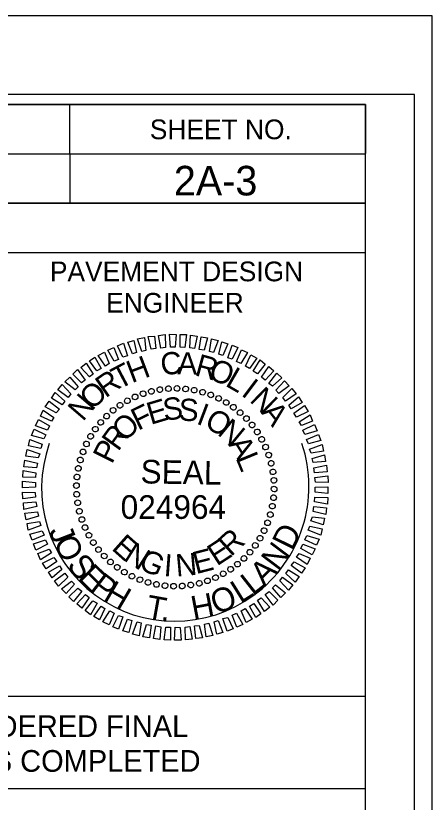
# Model space of a CAD drawing. Extents: x 1640342 to 1730599, y 538663 to 843747.
# Drawn here: x 1730156.25 to 1730177.39, y 539804.62 to 539844.5 of the extents above; entities that cross this region are included whole.
import ezdxf

# ---------------------------------------------------------------- set-up
doc = ezdxf.new("R2010")
doc.units = 0
for name, color, linetype in [('Sheet Data Field CELL', 7, 'Continuous'), ('Sheet PE Seal Cell', 7, 'Continuous'), ('Sheet Plan CELL', 7, 'Continuous'), ('Sheet Plan Layout CELL', 7, 'Continuous'), ('Sheet Plot Border Inside CELL', 7, 'Continuous'), ('Sheet Plot Border Outside CELL', 7, 'Continuous'), ('Sheet Sticker Exception Certification CELL', 7, 'Continuous')]:
    doc.layers.add(name, color=color, linetype=linetype)

msp = doc.modelspace()

# ---------------------------------------------------------------- linework, layer by layer
at = {"layer": 'Sheet PE Seal Cell'}
for p, q in [((1730162.709, 539825.337), (1730162.709, 539825.337)), ((1730163.129, 539825.457), (1730163.129, 539825.457)), ((1730163.569, 539825.537), (1730163.569, 539825.537)), ((1730163.999, 539825.597), (1730163.999, 539825.597)), ((1730164.439, 539825.607), (1730164.439, 539825.607)), ((1730164.879, 539825.577), (1730164.879, 539825.577)), ((1730165.309, 539825.507), (1730165.309, 539825.507)), ((1730165.729, 539825.417), (1730165.729, 539825.417)), ((1730166.149, 539825.277), (1730166.149, 539825.277)), ((1730161.919, 539824.977), (1730161.919, 539824.977)), ((1730162.309, 539825.177), (1730162.309, 539825.177)), ((1730166.549, 539825.097), (1730166.549, 539825.097)), ((1730166.939, 539824.897), (1730166.939, 539824.897)), ((1730161.189, 539824.497), (1730161.189, 539824.497)), ((1730161.539, 539824.747), (1730161.539, 539824.747)), ((1730167.299, 539824.647), (1730167.299, 539824.647)), ((1730160.859, 539824.197), (1730160.859, 539824.197)), ((1730167.649, 539824.377), (1730167.649, 539824.377)), ((1730167.959, 539824.077), (1730167.959, 539824.077)), ((1730160.559, 539823.887), (1730160.559, 539823.887)), ((1730168.259, 539823.747), (1730168.259, 539823.747)), ((1730160.289, 539823.537), (1730160.289, 539823.537)), ((1730168.509, 539823.397), (1730168.509, 539823.397)), ((1730160.039, 539823.177), (1730160.039, 539823.177)), ((1730168.739, 539823.017), (1730168.739, 539823.017)), ((1730159.839, 539822.787), (1730159.839, 539822.787)), ((1730168.939, 539822.627), (1730168.939, 539822.627)), ((1730159.659, 539822.387), (1730159.659, 539822.387)), ((1730169.099, 539822.227), (1730169.099, 539822.227)), ((1730159.519, 539821.967), (1730159.519, 539821.967)), ((1730169.219, 539821.807), (1730169.219, 539821.807)), ((1730159.429, 539821.547), (1730159.429, 539821.547)), ((1730169.299, 539821.367), (1730169.299, 539821.367)), ((1730159.359, 539821.117), (1730159.359, 539821.117)), ((1730169.359, 539820.937), (1730169.359, 539820.937)), ((1730159.329, 539820.677), (1730159.329, 539820.677)), ((1730169.369, 539820.497), (1730169.369, 539820.497)), ((1730159.339, 539820.237), (1730159.339, 539820.237)), ((1730169.339, 539820.057), (1730169.339, 539820.057)), ((1730159.399, 539819.807), (1730159.399, 539819.807)), ((1730169.269, 539819.627), (1730169.269, 539819.627)), ((1730159.479, 539819.367), (1730159.479, 539819.367)), ((1730159.599, 539818.947), (1730159.599, 539818.947)), ((1730169.179, 539819.207), (1730169.179, 539819.207)), ((1730159.759, 539818.547), (1730159.759, 539818.547)), ((1730169.039, 539818.787), (1730169.039, 539818.787)), ((1730159.959, 539818.157), (1730159.959, 539818.157)), ((1730168.859, 539818.387), (1730168.859, 539818.387)), ((1730160.189, 539817.777), (1730160.189, 539817.777)), ((1730168.409, 539817.637), (1730168.409, 539817.637)), ((1730168.659, 539817.997), (1730168.659, 539817.997)), ((1730160.439, 539817.427), (1730160.439, 539817.427)), ((1730168.139, 539817.287), (1730168.139, 539817.287)), ((1730160.739, 539817.097), (1730160.739, 539817.097)), ((1730167.839, 539816.977), (1730167.839, 539816.977)), ((1730161.049, 539816.797), (1730161.049, 539816.797)), ((1730161.399, 539816.527), (1730161.399, 539816.527)), ((1730167.509, 539816.677), (1730167.509, 539816.677)), ((1730161.759, 539816.277), (1730161.759, 539816.277)), ((1730162.149, 539816.077), (1730162.149, 539816.077)), ((1730166.779, 539816.197), (1730166.779, 539816.197)), ((1730167.159, 539816.427), (1730167.159, 539816.427)), ((1730162.549, 539815.897), (1730162.549, 539815.897)), ((1730162.969, 539815.757), (1730162.969, 539815.757)), ((1730163.389, 539815.667), (1730163.389, 539815.667)), ((1730165.129, 539815.637), (1730165.129, 539815.637)), ((1730165.569, 539815.717), (1730165.569, 539815.717)), ((1730165.989, 539815.837), (1730165.989, 539815.837)), ((1730166.389, 539815.997), (1730166.389, 539815.997)), ((1730163.819, 539815.597), (1730163.819, 539815.597)), ((1730164.259, 539815.567), (1730164.259, 539815.567)), ((1730164.699, 539815.577), (1730164.699, 539815.577))]:
    msp.add_line(p, q, dxfattribs=at)
for points in [[(1730162.169, 539827.347), (1730161.939, 539827.947), (1730162.249, 539828.037), (1730162.379, 539827.417)], [(1730162.649, 539827.477), (1730162.439, 539828.107), (1730162.779, 539828.177), (1730162.859, 539827.527)], [(1730163.129, 539827.587), (1730162.969, 539828.227), (1730163.299, 539828.257), (1730163.369, 539827.617)], [(1730163.609, 539827.647), (1730163.499, 539828.287), (1730163.839, 539828.327), (1730163.849, 539827.677)], [(1730164.109, 539827.697), (1730164.059, 539828.347), (1730164.389, 539828.337), (1730164.349, 539827.687)], [(1730164.589, 539827.687), (1730164.589, 539828.337), (1730164.919, 539828.327), (1730164.829, 539827.677)], [(1730165.089, 539827.657), (1730165.129, 539828.307), (1730165.459, 539828.247), (1730165.329, 539827.617)], [(1730165.569, 539827.577), (1730165.659, 539828.217), (1730165.989, 539828.167), (1730165.809, 539827.547)], [(1730166.079, 539827.467), (1730166.179, 539828.117), (1730166.519, 539828.037), (1730166.289, 539827.417)], [(1730161.239, 539826.977), (1730160.919, 539827.537), (1730161.229, 539827.677), (1730161.459, 539827.067)], [(1730161.679, 539827.187), (1730161.419, 539827.767), (1730161.719, 539827.887), (1730161.929, 539827.247)], [(1730166.559, 539827.337), (1730166.709, 539827.957), (1730167.019, 539827.857), (1730166.769, 539827.267)], [(1730167.009, 539827.157), (1730167.239, 539827.787), (1730167.519, 539827.667), (1730167.239, 539827.087)], [(1730160.809, 539826.737), (1730160.439, 539827.277), (1730160.749, 539827.437), (1730160.999, 539826.857)], [(1730167.459, 539826.967), (1730167.709, 539827.557), (1730168.019, 539827.417), (1730167.679, 539826.857)], [(1730167.919, 539826.737), (1730168.189, 539827.307), (1730168.489, 539827.137), (1730168.109, 539826.617)], [(1730159.989, 539826.187), (1730159.559, 539826.667), (1730159.829, 539826.877), (1730160.179, 539826.317)], [(1730160.369, 539826.487), (1730159.999, 539826.997), (1730160.259, 539827.187), (1730160.589, 539826.607)], [(1730168.309, 539826.467), (1730168.659, 539827.047), (1730168.919, 539826.837), (1730168.529, 539826.347)], [(1730159.589, 539825.877), (1730159.149, 539826.317), (1730159.389, 539826.557), (1730159.779, 539826.017)], [(1730168.719, 539826.167), (1730169.089, 539826.717), (1730169.349, 539826.497), (1730168.909, 539826.027)], [(1730159.259, 539825.527), (1730158.749, 539825.937), (1730158.999, 539826.167), (1730159.419, 539825.687)], [(1730169.099, 539825.857), (1730169.509, 539826.377), (1730169.749, 539826.137), (1730169.289, 539825.707)], [(1730158.909, 539825.147), (1730158.389, 539825.537), (1730158.609, 539825.797), (1730159.049, 539825.327)], [(1730169.459, 539825.507), (1730169.889, 539825.977), (1730170.129, 539825.737), (1730169.609, 539825.347)], [(1730158.609, 539824.767), (1730158.069, 539825.107), (1730158.259, 539825.397), (1730158.739, 539824.957)], [(1730169.809, 539825.147), (1730170.269, 539825.597), (1730170.479, 539825.327), (1730169.949, 539824.947)], [(1730158.309, 539824.367), (1730157.749, 539824.667), (1730157.949, 539824.947), (1730158.469, 539824.547)], [(1730170.109, 539824.757), (1730170.599, 539825.177), (1730170.789, 539824.887), (1730170.229, 539824.567)], [(1730158.069, 539823.937), (1730157.499, 539824.187), (1730157.649, 539824.497), (1730158.189, 539824.127)], [(1730170.369, 539824.347), (1730170.899, 539824.727), (1730171.089, 539824.427), (1730170.509, 539824.147)], [(1730157.869, 539823.477), (1730157.249, 539823.707), (1730157.399, 539824.017), (1730157.969, 539823.697)], [(1730170.629, 539823.907), (1730171.189, 539824.257), (1730171.319, 539823.947), (1730170.749, 539823.717)], [(1730170.829, 539823.477), (1730171.419, 539823.777), (1730171.549, 539823.457), (1730170.929, 539823.257)], [(1730157.669, 539823.037), (1730157.049, 539823.217), (1730157.179, 539823.527), (1730157.779, 539823.247)], [(1730171.009, 539823.007), (1730171.619, 539823.267), (1730171.729, 539822.957), (1730171.109, 539822.797)], [(1730157.519, 539822.557), (1730156.899, 539822.687), (1730156.969, 539823.017), (1730157.599, 539822.767)], [(1730157.389, 539822.077), (1730156.769, 539822.157), (1730156.839, 539822.497), (1730157.469, 539822.287)], [(1730171.169, 539822.527), (1730171.809, 539822.757), (1730171.869, 539822.427), (1730171.239, 539822.317)], [(1730171.289, 539822.047), (1730171.919, 539822.237), (1730171.979, 539821.897), (1730171.349, 539821.837)], [(1730157.309, 539821.567), (1730156.669, 539821.627), (1730156.709, 539821.967), (1730157.359, 539821.807)], [(1730171.379, 539821.567), (1730172.029, 539821.707), (1730172.059, 539821.367), (1730171.419, 539821.327)], [(1730157.259, 539821.087), (1730156.609, 539821.107), (1730156.629, 539821.437), (1730157.279, 539821.327)], [(1730157.249, 539820.587), (1730156.599, 539820.557), (1730156.599, 539820.897), (1730157.249, 539820.827)], [(1730171.439, 539821.087), (1730172.089, 539821.167), (1730172.109, 539820.827), (1730171.459, 539820.847)], [(1730171.449, 539820.587), (1730172.099, 539820.617), (1730172.099, 539820.277), (1730171.449, 539820.347)], [(1730157.259, 539820.087), (1730156.609, 539820.007), (1730156.589, 539820.347), (1730157.239, 539820.327)], [(1730171.439, 539820.087), (1730172.089, 539820.067), (1730172.069, 539819.737), (1730171.419, 539819.847)], [(1730157.319, 539819.607), (1730156.669, 539819.467), (1730156.639, 539819.807), (1730157.279, 539819.847)], [(1730157.409, 539819.127), (1730156.779, 539818.937), (1730156.719, 539819.277), (1730157.349, 539819.337)], [(1730171.389, 539819.607), (1730172.029, 539819.547), (1730171.989, 539819.207), (1730171.339, 539819.367)], [(1730157.529, 539818.647), (1730156.889, 539818.417), (1730156.829, 539818.747), (1730157.459, 539818.857)], [(1730171.309, 539819.097), (1730171.929, 539819.017), (1730171.859, 539818.677), (1730171.229, 539818.887)], [(1730171.179, 539818.617), (1730171.799, 539818.487), (1730171.729, 539818.157), (1730171.099, 539818.407)], [(1730157.689, 539818.167), (1730157.079, 539817.907), (1730156.969, 539818.217), (1730157.589, 539818.377)], [(1730171.029, 539818.137), (1730171.649, 539817.957), (1730171.519, 539817.647), (1730170.919, 539817.927)], [(1730157.869, 539817.697), (1730157.279, 539817.397), (1730157.149, 539817.717), (1730157.769, 539817.917)], [(1730170.829, 539817.697), (1730171.449, 539817.467), (1730171.299, 539817.157), (1730170.729, 539817.477)], [(1730158.069, 539817.267), (1730157.509, 539816.917), (1730157.379, 539817.227), (1730157.949, 539817.457)], [(1730170.629, 539817.237), (1730171.199, 539816.987), (1730171.049, 539816.677), (1730170.509, 539817.047)], [(1730158.329, 539816.827), (1730157.799, 539816.447), (1730157.609, 539816.747), (1730158.189, 539817.027)], [(1730158.589, 539816.417), (1730158.099, 539815.997), (1730157.909, 539816.287), (1730158.469, 539816.607)], [(1730170.389, 539816.807), (1730170.949, 539816.507), (1730170.749, 539816.227), (1730170.229, 539816.627)], [(1730158.889, 539816.027), (1730158.429, 539815.577), (1730158.219, 539815.847), (1730158.749, 539816.227)], [(1730170.089, 539816.407), (1730170.629, 539816.067), (1730170.439, 539815.777), (1730169.959, 539816.217)], [(1730159.239, 539815.667), (1730158.809, 539815.197), (1730158.569, 539815.437), (1730159.089, 539815.827)], [(1730169.439, 539815.647), (1730169.949, 539815.237), (1730169.699, 539815.007), (1730169.279, 539815.487)], [(1730169.789, 539816.027), (1730170.309, 539815.637), (1730170.089, 539815.377), (1730169.649, 539815.847)], [(1730159.599, 539815.317), (1730159.189, 539814.797), (1730158.949, 539815.037), (1730159.409, 539815.467)], [(1730169.109, 539815.297), (1730169.549, 539814.857), (1730169.309, 539814.617), (1730168.919, 539815.157)], [(1730159.979, 539815.007), (1730159.609, 539814.457), (1730159.349, 539814.677), (1730159.789, 539815.147)], [(1730168.709, 539814.987), (1730169.139, 539814.507), (1730168.869, 539814.297), (1730168.519, 539814.857)], [(1730160.389, 539814.707), (1730160.039, 539814.127), (1730159.779, 539814.337), (1730160.169, 539814.827)], [(1730160.779, 539814.437), (1730160.509, 539813.867), (1730160.209, 539814.037), (1730160.589, 539814.557)], [(1730168.329, 539814.687), (1730168.699, 539814.177), (1730168.439, 539813.987), (1730168.109, 539814.567)], [(1730161.239, 539814.207), (1730160.989, 539813.617), (1730160.679, 539813.757), (1730161.019, 539814.317)], [(1730161.689, 539814.017), (1730161.459, 539813.387), (1730161.179, 539813.507), (1730161.459, 539814.087)], [(1730167.459, 539814.197), (1730167.779, 539813.637), (1730167.469, 539813.497), (1730167.239, 539814.107)], [(1730167.889, 539814.437), (1730168.259, 539813.897), (1730167.949, 539813.737), (1730167.699, 539814.317)], [(1730162.139, 539813.837), (1730161.989, 539813.217), (1730161.679, 539813.317), (1730161.929, 539813.907)], [(1730162.619, 539813.707), (1730162.519, 539813.057), (1730162.179, 539813.137), (1730162.409, 539813.757)], [(1730166.049, 539813.697), (1730166.259, 539813.067), (1730165.919, 539812.997), (1730165.839, 539813.647)], [(1730166.529, 539813.827), (1730166.759, 539813.227), (1730166.449, 539813.137), (1730166.319, 539813.757)], [(1730167.019, 539813.987), (1730167.279, 539813.407), (1730166.979, 539813.287), (1730166.769, 539813.927)], [(1730163.129, 539813.597), (1730163.039, 539812.957), (1730162.709, 539813.007), (1730162.889, 539813.627)], [(1730163.609, 539813.517), (1730163.569, 539812.867), (1730163.239, 539812.927), (1730163.369, 539813.557)], [(1730164.109, 539813.487), (1730164.109, 539812.837), (1730163.779, 539812.847), (1730163.869, 539813.497)], [(1730164.589, 539813.477), (1730164.639, 539812.827), (1730164.309, 539812.837), (1730164.349, 539813.487)], [(1730165.089, 539813.527), (1730165.199, 539812.887), (1730164.859, 539812.847), (1730164.849, 539813.497)], [(1730165.569, 539813.587), (1730165.729, 539812.947), (1730165.399, 539812.917), (1730165.329, 539813.557)]]:
    msp.add_lwpolyline(points, close=True, dxfattribs=at)
for centre, major_axis in [((1730163.136, 539825.454), (-0.035, 0.14)), ((1730163.565, 539825.541), (-0.023, 0.142)), ((1730163.999, 539825.591), (-0.01, 0.144)), ((1730164.437, 539825.602), (0.003, 0.144)), ((1730164.874, 539825.575), (0.015, 0.143)), ((1730165.306, 539825.511), (0.027, 0.141)), ((1730162.309, 539825.169), (-0.059, 0.132)), ((1730162.716, 539825.33), (-0.047, 0.136)), ((1730165.732, 539825.409), (0.04, 0.138)), ((1730166.147, 539825.27), (0.052, 0.134)), ((1730166.548, 539825.095), (0.063, 0.129)), ((1730161.544, 539824.745), (-0.081, 0.119)), ((1730161.918, 539824.974), (-0.07, 0.126)), ((1730166.933, 539824.886), (0.074, 0.123)), ((1730161.193, 539824.485), (-0.091, 0.112)), ((1730167.298, 539824.645), (0.085, 0.116)), ((1730167.64, 539824.373), (0.094, 0.109)), ((1730160.564, 539823.878), (-0.109, 0.094)), ((1730160.865, 539824.195), (-0.1, 0.104)), ((1730167.958, 539824.071), (0.104, 0.1)), ((1730160.291, 539823.535), (-0.116, 0.085)), ((1730168.247, 539823.744), (0.112, 0.091)), ((1730160.05, 539823.17), (-0.123, 0.074)), ((1730168.508, 539823.392), (0.119, 0.081)), ((1730159.841, 539822.786), (-0.129, 0.063)), ((1730168.736, 539823.019), (0.126, 0.07)), ((1730159.666, 539822.385), (-0.134, 0.052)), ((1730168.932, 539822.627), (0.132, 0.059)), ((1730159.528, 539821.97), (-0.138, 0.04)), ((1730169.092, 539822.22), (0.136, 0.047)), ((1730159.425, 539821.544), (-0.141, 0.027)), ((1730169.216, 539821.8), (0.14, 0.035)), ((1730159.361, 539821.111), (-0.143, 0.015)), ((1730169.304, 539821.372), (0.142, 0.023)), ((1730169.353, 539820.937), (0.144, 0.01)), ((1730159.334, 539820.674), (-0.144, 0.003)), ((1730169.365, 539820.499), (0.144, -0.003)), ((1730159.346, 539820.237), (-0.144, -0.01)), ((1730169.338, 539820.063), (0.143, -0.015)), ((1730159.395, 539819.802), (-0.142, -0.023)), ((1730169.273, 539819.63), (0.141, -0.027)), ((1730159.482, 539819.373), (-0.14, -0.035)), ((1730169.171, 539819.204), (0.138, -0.04)), ((1730159.607, 539818.954), (-0.136, -0.047)), ((1730169.032, 539818.789), (0.134, -0.052)), ((1730159.767, 539818.547), (-0.132, -0.059)), ((1730168.858, 539818.388), (0.129, -0.063)), ((1730159.962, 539818.155), (-0.126, -0.07)), ((1730168.649, 539818.004), (0.123, -0.074)), ((1730160.191, 539817.782), (-0.119, -0.081)), ((1730168.407, 539817.639), (0.116, -0.085)), ((1730160.451, 539817.43), (-0.112, -0.091)), ((1730160.741, 539817.103), (-0.104, -0.1)), ((1730168.135, 539817.296), (0.109, -0.094)), ((1730161.059, 539816.801), (-0.094, -0.109)), ((1730167.506, 539816.689), (0.091, -0.112)), ((1730167.834, 539816.979), (0.1, -0.104)), ((1730161.401, 539816.529), (-0.085, -0.116)), ((1730161.766, 539816.287), (-0.074, -0.123)), ((1730167.154, 539816.428), (0.081, -0.119)), ((1730162.15, 539816.079), (-0.063, -0.129)), ((1730162.552, 539815.904), (-0.052, -0.134)), ((1730166.39, 539816.005), (0.059, -0.132)), ((1730166.781, 539816.2), (0.07, -0.126)), ((1730162.967, 539815.765), (-0.04, -0.138)), ((1730163.392, 539815.663), (-0.027, -0.141)), ((1730163.825, 539815.598), (-0.015, -0.143)), ((1730164.262, 539815.572), (-0.003, -0.144)), ((1730164.699, 539815.583), (0.01, -0.144)), ((1730165.134, 539815.633), (0.023, -0.142)), ((1730165.563, 539815.72), (0.035, -0.14)), ((1730165.982, 539815.844), (0.047, -0.136))]:
    msp.add_ellipse(centre, major_axis=major_axis, ratio=0.999708, dxfattribs=at)
at = {"layer": 'Sheet Plan CELL'}
for p, q in [((1730158.985, 539839.988), (1730158.995, 539834.988)), ((1730133.98, 539837.493), (1730173.99, 539837.491)), ((1730133.983, 539834.986), (1730173.99, 539834.991)), ((1730133.983, 539834.986), (1730173.99, 539834.991))]:
    msp.add_line(p, q, dxfattribs=at)
for points in [[(1729873.99, 539630.001), (1729873.985, 539839.996), (1730133.983, 539840.003), (1730133.985, 539809.991), (1730173.993, 539809.988), (1730173.993, 539630.001)], [(1730173.998, 539840.001), (1729873.99, 539840.001), (1729873.99, 539630.001), (1730173.993, 539630.001)], [(1730133.983, 539840.003), (1730173.998, 539840.001), (1730173.99, 539834.991), (1730133.983, 539834.986)], [(1730153.993, 539832.488), (1730173.99, 539832.491), (1730173.993, 539809.988), (1730153.993, 539809.986)]]:
    msp.add_lwpolyline(points, close=True, dxfattribs=at)
at = {"layer": 'Sheet Plan Layout CELL'}
msp.add_lwpolyline([(1730126.14, 539797.703), (1730173.995, 539797.703), (1730174, 539840.001), (1730126.14, 539840.001)], close=True, dxfattribs=at)
at = {"layer": 'Sheet Plot Border Inside CELL'}
msp.add_lwpolyline([(1729843.293, 539629.498), (1730176.49, 539629.501), (1730176.493, 539840.498), (1729843.293, 539840.498)], close=True, dxfattribs=at)
at = {"layer": 'Sheet Plot Border Outside CELL'}
msp.add_lwpolyline([(1729840.693, 539625.498), (1730177.393, 539625.498), (1730177.393, 539844.498), (1729840.693, 539844.498)], close=True, dxfattribs=at)
msp.add_ellipse((1730164.349, 539820.587), major_axis=(4.509, 5.104), ratio=0.993455, start_param=1.958957, end_param=5.764947, dxfattribs=at)
at = {"layer": 'Sheet Sticker Exception Certification CELL'}
for p, q in [((1730133.985, 539809.991), (1730173.993, 539809.991)), ((1730133.985, 539809.991), (1730173.993, 539809.991)), ((1730173.993, 539809.988), (1730173.993, 539805.288)), ((1730173.993, 539809.988), (1730173.993, 539805.288)), ((1730173.993, 539805.291), (1730133.985, 539805.291)), ((1730173.993, 539805.291), (1730133.985, 539805.291))]:
    msp.add_line(p, q, dxfattribs=at)

# ---------------------------------------------------------------- texts
at = {"layer": 'Sheet Data Field CELL'}
msp.add_text('2A-3', height=1.5, rotation=0, dxfattribs=at).set_placement((1730164.276, 539835.386))
at = {"layer": 'Sheet PE Seal Cell'}
for s, height, rotation, p in [('H', 1.128, 20.6195, (1730162.139, 539825.857)), ('C', 1.128, 6.2199, (1730163.659, 539826.257)), ('A', 1.128, 359.0203, (1730164.449, 539826.317)), ('R', 1.128, 344.6211, (1730165.289, 539826.277)), ('T', 1.128, 27.8198, (1730161.489, 539825.527)), ('O', 1.128, 337.4212, (1730165.959, 539826.127)), ('R', 1.128, 35.0205, (1730160.809, 539825.087)), ('L', 1.128, 330.2209, (1730166.839, 539825.757)), ('I', 1.128, 323.0201, (1730167.649, 539825.277)), ('O', 1.128, 42.2217, (1730160.119, 539824.467)), ('N', 1.128, 315.8189, (1730168.079, 539824.967)), ('N', 1.128, 49.4235, (1730159.659, 539823.887)), ('F', 1.128, 25.967, (1730162.459, 539823.447)), ('E', 1.128, 16.6111, (1730163.099, 539823.747)), ('S', 1.128, 7.2556, (1730163.789, 539823.957)), ('S', 1.128, 357.9004, (1730164.509, 539823.967)), ('I', 1.128, 339.1896, (1730165.369, 539823.827)), ('O', 1.128, 329.8335, (1730165.769, 539823.687)), ('A', 1.128, 308.6172, (1730168.669, 539824.377)), ('O', 1.128, 44.6812, (1730161.799, 539822.857)), ('N', 1.128, 320.4766, (1730166.439, 539823.287)), ('R', 1.128, 54.0397, (1730161.449, 539822.367)), ('P', 1.128, 63.3989, (1730161.129, 539821.727)), ('A', 1.128, 301.7603, (1730167.009, 539822.767)), ('L', 1.128, 292.4008, (1730167.399, 539822.077)), ('SEAL', 1.1996, 359, (1730162.579, 539820.787)), ('J', 1.2, 291.2124, (1730157.911, 539818.381)), ('D', 1.2, 63.6039, (1730170.285, 539817.321)), ('O', 1.2, 296.4669, (1730158.135, 539817.804)), ('E', 1.128, 318.2769, (1730161.069, 539817.457)), ('R', 1.128, 42.4814, (1730167.169, 539817.037)), ('N', 1.128, 327.634, (1730161.669, 539816.917)), ('E', 1.128, 33.1241, (1730166.459, 539816.567)), ('N', 1.2, 53.0513, (1730169.575, 539816.278)), ('G', 1.128, 336.9902, (1730162.429, 539816.467)), ('N', 1.128, 5.0564, (1730164.409, 539816.057)), ('E', 1.128, 14.4118, (1730165.399, 539816.177)), ('S', 1.2, 308.0413, (1730158.806, 539816.622)), ('I', 1.128, 355.7012, (1730163.739, 539816.087)), ('E', 1.2, 315.3853, (1730159.35, 539815.953)), ('A', 1.2, 44.3588, (1730168.854, 539815.529)), ('P', 1.2, 322.5143, (1730159.955, 539815.375)), ('L', 1.2, 38.1871, (1730168.277, 539815.067)), ('H', 1.2, 329.641, (1730160.627, 539814.877)), ('L', 1.2, 32.0108, (1730167.655, 539814.67)), ('O', 1.2, 20.6113, (1730166.41, 539814.123)), ('T', 1.2, 349.8271, (1730162.805, 539813.957)), ('H', 1.2, 10.7371, (1730165.267, 539813.858)), ('.', 1.2, 356.6032, (1730163.595, 539813.827))]:
    msp.add_text(s, height=height, rotation=rotation, dxfattribs=at).set_placement(p)
msp.add_text('024964', height=1.1996, dxfattribs=at).set_placement((1730161.574, 539818.985))
at = {"layer": 'Sheet Plan CELL'}
for s, height, p in [('SHEET NO.', 1, (1730163.055, 539838.236)), ('PAVEMENT DESIGN', 1.00002, (1730157.984, 539831.033)), ('ENGINEER', 1, (1730160.838, 539829.441))]:
    msp.add_text(s, height=height, rotation=0, dxfattribs=at).set_placement(p)
at = {"layer": 'Sheet Sticker Exception Certification CELL'}
for s, p in [('DOCUMENT NOT CONSIDERED FINAL', (1730138.199, 539807.922)), ('DOCUMENT NOT CONSIDERED FINAL', (1730138.199, 539807.922)), ('UNLESS ALL SIGNATURES COMPLETED', (1730137.185, 539806.162)), ('UNLESS ALL SIGNATURES COMPLETED', (1730137.185, 539806.162))]:
    msp.add_text(s, height=1.1, dxfattribs=at).set_placement(p)

doc.saveas('drawing.dxf')
